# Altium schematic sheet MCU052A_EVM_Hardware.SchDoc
size 431 x 279 mm; Date: Not shown in title block; ApprovedBy: Not shown in title block; CheckedBy: Not shown in title block; Author: Not shown in title block; CompanyName: Not shown in title block; Engineer: Not shown in title block; Organization: Not shown in title block; Address1: Not shown in title block; Address2: Not shown in title block; Address3: Not shown in title block; Address4: Not shown in title block; DocumentNumber: 1; Revision: Use project parameter SCH_Rev; SheetNumber: 2; SheetTotal: 2; PageSetup: Record=PageOptions¦CenterHorizontal=True¦CenterVertical=True¦PrintScale=1.00¦XCorrection=1.00¦YCorrection=1.00¦PrintKind=0¦BorderSize=5000000¦LeftOffset=0¦BottomOffset=0¦Orientation=2¦PaperLength=1000¦PaperWidth=1000¦Scale=100¦PaperSource=15¦PrintQuality=600¦MediaType=1¦DitherType=10¦PaperKind=Letter¦PrintScaleMode=1
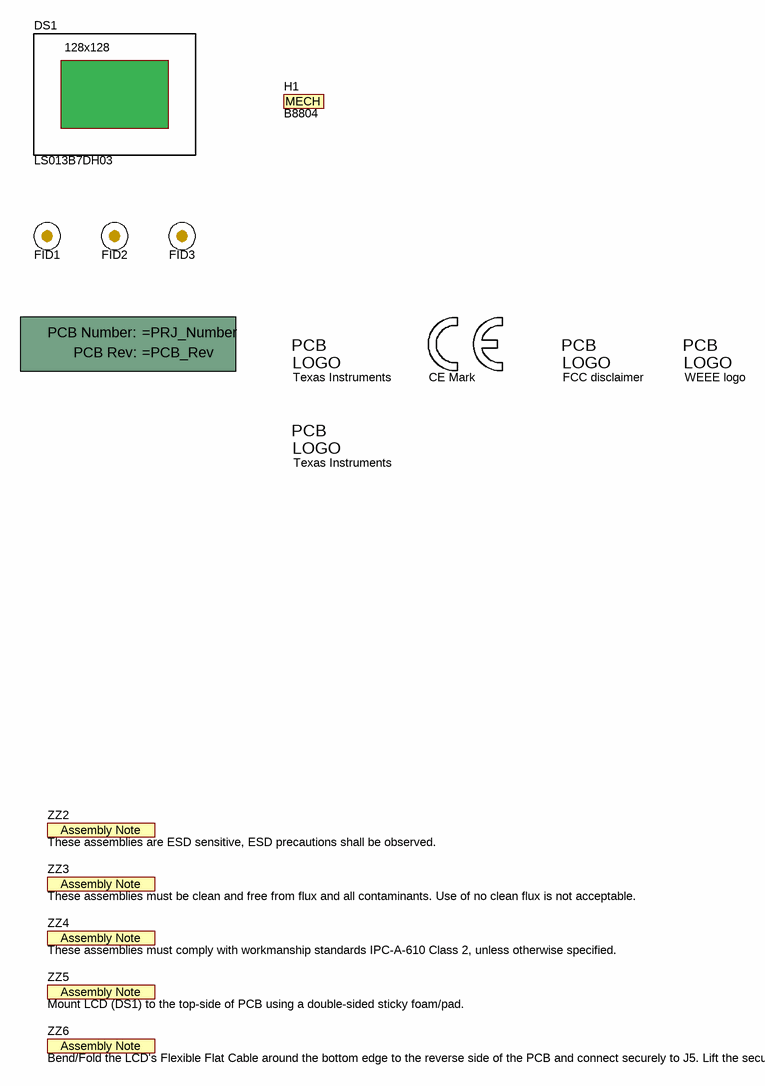
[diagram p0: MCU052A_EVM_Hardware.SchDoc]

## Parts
!PCB1  Printed Circuit Board  (value not drawn)  (mechanical)
DS1  LS013B7DH03  [Sharp_LS013B7DH03]
FID1  Fiducial  [Fiducial10-20]  (value not drawn)
FID2  Fiducial  [Fiducial10-20]  (value not drawn)
FID3  Fiducial  [Fiducial10-20]  (value not drawn)
H1  B8804  (mechanical)
Logo1  CE Mark  [CE_Mark_5mm]  (no BOM)
Logo2  Texas Instruments  [TI_Symbol_Overlay_Small]  (no BOM)
Logo3  FCC disclaimer  [FCC_disclaimer_stacked]  (no BOM)
Logo4  WEEE logo  [WEEE_Minimum]  (no BOM)
Logo5  Texas Instruments  [TI_Stacked_Overlay_Small_Vertical]  (no BOM)
ZZ2  These assemblies are ESD sensitive, ESD precautions shall be observed.  [AssemblyNote]  (no BOM)
ZZ3  These assemblies must be clean and free from flux and all contaminants. Use of no clean flux is not acceptable.  [AssemblyNote]  (no BOM)
ZZ4  These assemblies must comply with workmanship standards IPC-A-610 Class 2, unless otherwise specified.  [AssemblyNote]  (no BOM)
ZZ5  Mount LCD (DS1) to the top-side of PCB using a double-sided sticky foam/pad.  [AssemblyNote]  (no BOM)
ZZ6  Bend/Fold the LCD's Flexible Flat Cable around the bottom edge to the reverse side of the PCB and connect securely to J5. Lift the securing tab on J5 vertically, insert the LCD flex cable, and push the securing tab down until a tactile click.  [AssemblyNote]  (no BOM)

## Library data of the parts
!PCB1 = CMP-0003618-2: Manufacturer: Any
DS1 = CMP-0067626-1: LCD Display Dot Pixels 128x128; Manufacturer: Sharp Microelectronics; CompType: LCD Module
FID1-FID3 = CMP-0077181-1: Fiducial mark.  There is nothing to buy or mount.
H1 = CMP-0080604-2: 1mm Thick, Doublesided Adhesive EVA Foam Pad (cut into 20mm x 20mm square pieces); Manufacturer: ZHEJIANG XINHENGTAI ADVANCED MATERIAL CO., LTD; Alternate PartNumber: 5952 3/4"X15YD; Alternate Manufacturer: 3M; CompType: Mechanical
Logo1 = CMP-0074844-1: SymbolCreator: a0412235
Logo2 = CMP-0074838-1: Texas Instrument Corporate Signature; SymbolCreator: a0412235; Lib Reference: TI_Logo; Library Reference: Logo
Logo3 = CMP-0074847-1: FCC_disclaimer; Library Reference: Logo
Logo4 = CMP-0074769-1
Logo5 = CMP-0074838-1: Texas Instrument Corporate Signature; Library Reference: Logo; SymbolCreator: a0412235; Lib Reference: TI_Logo
ZZ2 ZZ5 ZZ6 = CMP-0077236-1
ZZ3 = CMP-0077237-1
ZZ4 = CMP-0077238-1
